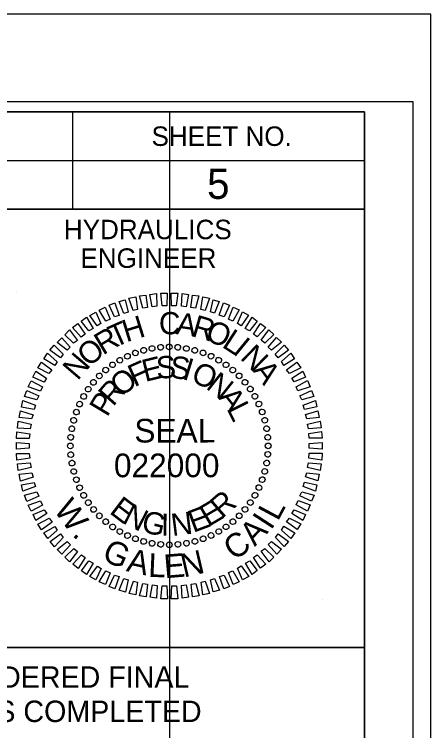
# Model space of a CAD drawing. Extents: x 10070 to 15319, y 8517 to 10343.
# Drawn here: x 14785 to 14891.9, y 9432.8 to 9616.7 of the extents above; entities that cross this region are included whole.
import ezdxf

# ---------------------------------------------------------------- set-up
doc = ezdxf.new("R2010")
doc.units = 0
for name, color, linetype in [('Default', 7, 'Continuous'), ('Scratch_Level_3', 7, 'Continuous'), ('Scratch_Level_4', 7, 'Continuous'), ('Sheet Cutting Line CELL', 7, 'Continuous'), ('Sheet Data Field CELL', 7, 'Continuous'), ('Sheet Plot Border Inside CELL', 7, 'Continuous'), ('Sheet Plot Border Outside CELL', 7, 'Continuous'), ('Sheet Profile CELL', 7, 'Continuous'), ('Sheet Profile Grid Major CELL', 7, 'Continuous'), ('Sheet Sticker Exception Certification CELL', 7, 'Continuous')]:
    doc.layers.add(name, color=color, linetype=linetype)

msp = doc.modelspace()

# ---------------------------------------------------------------- linework, layer by layer
at = {"layer": 'Default'}
for p, q in [((14785.51, 9545.45), (14785.51, 9545.45)), ((14818.22, 9530.48), (14818.22, 9530.48)), ((14820.4, 9530.94), (14820.4, 9530.94)), ((14829.21, 9530.94), (14829.21, 9530.94)), ((14814.07, 9528.96), (14814.07, 9528.96)), ((14816.09, 9529.82), (14816.09, 9529.82)), ((14841.16, 9525.43), (14841.16, 9525.43)), ((14806.83, 9523.9), (14806.83, 9523.9)), ((14805.31, 9522.28), (14805.31, 9522.28)), ((14804, 9520.5), (14804, 9520.5)), ((14845.61, 9520.52), (14845.61, 9520.52)), ((14802.78, 9518.63), (14802.78, 9518.63)), ((14846.83, 9518.65), (14846.83, 9518.65)), ((14801.77, 9516.66), (14801.77, 9516.66)), ((14847.84, 9516.67), (14847.84, 9516.67)), ((14800.91, 9514.63), (14800.91, 9514.63)), ((14848.7, 9514.65), (14848.7, 9514.65)), ((14800.26, 9512.5), (14800.26, 9512.5)), ((14849.36, 9512.52), (14849.36, 9512.52)), ((14799.8, 9510.33), (14799.8, 9510.33)), ((14849.82, 9510.35), (14849.82, 9510.35)), ((14799.5, 9508.15), (14799.5, 9508.15)), ((14850.12, 9508.17), (14850.12, 9508.17)), ((14799.4, 9505.92), (14799.4, 9505.92)), ((14824.81, 9505.93), (14824.81, 9505.93)), ((14850.23, 9505.94), (14850.23, 9505.94)), ((14799.5, 9503.69), (14799.5, 9503.69)), ((14850.13, 9503.72), (14850.13, 9503.72)), ((14799.81, 9501.52), (14799.81, 9501.52)), ((14849.82, 9501.54), (14849.82, 9501.54)), ((14800.26, 9499.34), (14800.26, 9499.34)), ((14849.37, 9499.36), (14849.37, 9499.36)), ((14800.92, 9497.21), (14800.92, 9497.21)), ((14848.71, 9497.23), (14848.71, 9497.23)), ((14801.78, 9495.19), (14801.78, 9495.19)), ((14847.85, 9495.21), (14847.85, 9495.21)), ((14802.8, 9493.22), (14802.8, 9493.22)), ((14846.84, 9493.23), (14846.84, 9493.23)), ((14804.01, 9491.34), (14804.01, 9491.34)), ((14845.62, 9491.36), (14845.62, 9491.36)), ((14805.33, 9489.57), (14805.33, 9489.57)), ((14844.31, 9489.59), (14844.31, 9489.59)), ((14806.85, 9487.95), (14806.85, 9487.95)), ((14808.47, 9486.43), (14808.47, 9486.43)), ((14841.17, 9486.45), (14841.17, 9486.45)), ((14842.79, 9487.97), (14842.79, 9487.97)), ((14810.24, 9485.12), (14810.24, 9485.12)), ((14839.4, 9485.13), (14839.4, 9485.13)), ((14812.11, 9483.91), (14812.11, 9483.91)), ((14814.09, 9482.89), (14814.09, 9482.89)), ((14835.55, 9482.9), (14835.55, 9482.9)), ((14837.53, 9483.92), (14837.53, 9483.92)), ((14816.11, 9482.03), (14816.11, 9482.03)), ((14818.24, 9481.38), (14818.24, 9481.38)), ((14820.42, 9480.92), (14820.42, 9480.92)), ((14829.23, 9480.93), (14829.23, 9480.93)), ((14831.4, 9481.38), (14831.4, 9481.38)), ((14833.53, 9482.04), (14833.53, 9482.04)), ((14822.59, 9480.62), (14822.59, 9480.62)), ((14824.82, 9480.52), (14824.82, 9480.52)), ((14827.05, 9480.62), (14827.05, 9480.62)), ((14864.11, 9466.41), (14864.11, 9466.41))]:
    msp.add_line(p, q, dxfattribs=at)
for points in [[(14820.44, 9541.62), (14819.83, 9544.81), (14821.51, 9545.06), (14821.66, 9541.77)], [(14822.97, 9541.88), (14822.62, 9545.17), (14824.29, 9545.17), (14824.19, 9541.88)], [(14825.4, 9541.88), (14825.3, 9545.17), (14826.97, 9545.17), (14826.62, 9541.88)], [(14827.94, 9541.78), (14828.09, 9545.07), (14829.76, 9544.81), (14829.15, 9541.62)], [(14813.15, 9539.95), (14811.94, 9542.98), (14813.51, 9543.44), (14814.22, 9540.3)], [(14815.58, 9540.66), (14814.47, 9543.85), (14816.19, 9544.2), (14816.65, 9540.91)], [(14818.01, 9541.27), (14817.15, 9544.45), (14818.82, 9544.66), (14819.23, 9541.42)], [(14830.37, 9541.42), (14830.77, 9544.66), (14832.44, 9544.46), (14831.58, 9541.27)], [(14832.95, 9540.92), (14833.4, 9544.21), (14835.12, 9543.85), (14834.01, 9540.66)], [(14835.38, 9540.31), (14836.09, 9543.45), (14837.66, 9542.99), (14836.44, 9539.96)], [(14808.5, 9537.97), (14806.83, 9540.81), (14808.39, 9541.51), (14809.61, 9538.48)], [(14810.72, 9539.09), (14809.36, 9542.02), (14810.82, 9542.63), (14811.94, 9539.44)], [(14837.66, 9539.45), (14838.77, 9542.64), (14840.24, 9542.03), (14838.87, 9539.1)], [(14839.99, 9538.49), (14841.2, 9541.53), (14842.77, 9540.82), (14841.1, 9537.98)], [(14806.32, 9536.76), (14804.4, 9539.44), (14805.97, 9540.3), (14807.28, 9537.36)], [(14842.32, 9537.38), (14843.63, 9540.31), (14845.2, 9539.45), (14843.28, 9536.77)], [(14804.14, 9535.44), (14802.22, 9537.97), (14803.54, 9538.98), (14805.26, 9536.05)], [(14844.34, 9536.06), (14846.06, 9539), (14847.38, 9537.99), (14845.45, 9535.46)], [(14802.22, 9533.87), (14799.99, 9536.3), (14801.36, 9537.36), (14803.18, 9534.58)], [(14846.42, 9534.59), (14848.24, 9537.38), (14849.61, 9536.32), (14847.38, 9533.89)], [(14800.25, 9532.3), (14797.97, 9534.47), (14799.18, 9535.69), (14801.21, 9533.01)], [(14848.39, 9533.03), (14850.42, 9535.71), (14851.63, 9534.5), (14849.35, 9532.32)], [(14798.58, 9530.47), (14796, 9532.5), (14797.21, 9533.71), (14799.39, 9531.28)], [(14850.22, 9531.31), (14852.39, 9533.74), (14853.61, 9532.52), (14851.03, 9530.5)], [(14796.86, 9528.5), (14794.17, 9530.47), (14795.29, 9531.79), (14797.57, 9529.46)], [(14852.04, 9529.48), (14854.32, 9531.81), (14855.43, 9530.5), (14852.75, 9528.52)], [(14795.39, 9526.57), (14792.61, 9528.24), (14793.57, 9529.71), (14796, 9527.54)], [(14853.61, 9527.56), (14856.04, 9529.74), (14857, 9528.27), (14854.22, 9526.6)], [(14793.92, 9524.5), (14791.04, 9525.97), (14792, 9527.43), (14794.68, 9525.46)], [(14854.93, 9525.49), (14857.61, 9527.46), (14858.57, 9525.99), (14855.69, 9524.52)], [(14792.71, 9522.32), (14789.82, 9523.54), (14790.53, 9525.1), (14793.32, 9523.28)], [(14856.29, 9523.31), (14859.08, 9525.13), (14859.79, 9523.56), (14856.9, 9522.35)], [(14791.75, 9519.99), (14788.61, 9521.1), (14789.32, 9522.67), (14792.25, 9521.11)], [(14857.36, 9521.13), (14860.29, 9522.7), (14861, 9521.13), (14857.86, 9520.02)], [(14790.79, 9517.71), (14787.65, 9518.57), (14788.25, 9520.14), (14791.29, 9518.78)], [(14858.32, 9518.8), (14861.36, 9520.17), (14861.97, 9518.6), (14858.83, 9517.74)], [(14790.08, 9515.28), (14786.89, 9515.89), (14787.24, 9517.56), (14790.43, 9516.35)], [(14859.18, 9516.38), (14862.37, 9517.59), (14862.73, 9515.92), (14859.54, 9515.31)], [(14789.47, 9512.85), (14786.28, 9513.21), (14786.64, 9514.93), (14789.83, 9513.92)], [(14859.79, 9513.95), (14862.98, 9514.96), (14863.33, 9513.24), (14860.15, 9512.88)], [(14789.07, 9510.27), (14785.83, 9510.52), (14786.03, 9512.24), (14789.32, 9511.49)], [(14860.3, 9511.52), (14863.59, 9512.28), (14863.79, 9510.56), (14860.55, 9510.3)], [(14788.87, 9507.84), (14785.58, 9507.84), (14785.68, 9509.56), (14788.97, 9509.06)], [(14860.65, 9509.09), (14863.94, 9509.59), (14864.05, 9507.87), (14860.75, 9507.87)], [(14788.87, 9505.31), (14785.58, 9505.06), (14785.58, 9506.78), (14788.87, 9506.52)], [(14860.76, 9506.55), (14864.05, 9506.81), (14864.05, 9505.09), (14860.76, 9505.34)], [(14788.97, 9502.78), (14785.68, 9502.27), (14785.58, 9503.99), (14788.87, 9503.99)], [(14860.76, 9504.02), (14864.05, 9504.02), (14863.95, 9502.3), (14860.66, 9502.81)], [(14789.33, 9500.35), (14786.04, 9499.59), (14785.83, 9501.31), (14789.07, 9501.56)], [(14860.56, 9501.59), (14863.8, 9501.34), (14863.59, 9499.62), (14860.3, 9500.38)], [(14789.83, 9497.92), (14786.64, 9496.91), (14786.29, 9498.63), (14789.48, 9498.98)], [(14860.15, 9499.01), (14863.34, 9498.66), (14862.99, 9496.94), (14859.8, 9497.95)], [(14790.44, 9495.49), (14787.25, 9494.27), (14786.9, 9495.94), (14790.09, 9496.55)], [(14859.54, 9496.58), (14862.73, 9495.97), (14862.38, 9494.3), (14859.19, 9495.52)], [(14791.3, 9493.06), (14788.27, 9491.69), (14787.66, 9493.26), (14790.8, 9494.12)], [(14858.84, 9494.15), (14861.98, 9493.29), (14861.37, 9491.72), (14858.33, 9493.09)], [(14792.27, 9490.73), (14789.33, 9489.16), (14788.62, 9490.73), (14791.76, 9491.84)], [(14857.88, 9491.87), (14861.02, 9490.76), (14860.31, 9489.19), (14857.37, 9490.76)], [(14793.33, 9488.55), (14790.55, 9486.73), (14789.84, 9488.3), (14792.72, 9489.52)], [(14856.92, 9489.54), (14859.8, 9488.33), (14859.09, 9486.76), (14856.31, 9488.58)], [(14794.7, 9486.38), (14792.02, 9484.4), (14791.05, 9485.87), (14793.94, 9487.34)], [(14855.7, 9487.37), (14858.59, 9485.9), (14857.63, 9484.43), (14854.94, 9486.4)], [(14796.02, 9484.3), (14793.59, 9482.13), (14792.62, 9483.59), (14795.41, 9485.26)], [(14854.23, 9485.29), (14857.02, 9483.62), (14856.06, 9482.15), (14853.63, 9484.33)], [(14797.59, 9482.38), (14795.31, 9480.05), (14794.19, 9481.37), (14796.88, 9483.34)], [(14852.77, 9483.36), (14855.45, 9481.39), (14854.34, 9480.07), (14852.06, 9482.4)], [(14799.41, 9480.56), (14797.23, 9478.13), (14796.02, 9479.34), (14798.6, 9481.37)], [(14851.05, 9481.39), (14853.63, 9479.37), (14852.41, 9478.15), (14850.24, 9480.58)], [(14801.23, 9478.84), (14799.21, 9476.15), (14797.99, 9477.37), (14800.27, 9479.55)], [(14849.38, 9479.57), (14851.66, 9477.39), (14850.44, 9476.18), (14848.41, 9478.86)], [(14803.21, 9477.27), (14801.39, 9474.48), (14800.02, 9475.55), (14802.24, 9477.98)], [(14847.4, 9478), (14849.63, 9475.57), (14848.26, 9474.5), (14846.44, 9477.29)], [(14805.28, 9475.8), (14803.56, 9472.87), (14802.25, 9473.88), (14804.17, 9476.41)], [(14845.48, 9476.43), (14847.4, 9473.9), (14846.09, 9472.88), (14844.37, 9475.82)], [(14807.31, 9474.49), (14805.99, 9471.55), (14804.42, 9472.41), (14806.35, 9475.09)], [(14809.64, 9473.37), (14808.42, 9470.34), (14806.85, 9471.04), (14808.52, 9473.88)], [(14841.13, 9473.89), (14842.8, 9471.06), (14841.23, 9470.35), (14840.01, 9473.39)], [(14843.3, 9475.11), (14845.23, 9472.43), (14843.66, 9471.57), (14842.34, 9474.5)], [(14811.97, 9472.41), (14810.85, 9469.22), (14809.39, 9469.83), (14810.75, 9472.77)], [(14814.25, 9471.55), (14813.54, 9468.41), (14811.97, 9468.87), (14813.18, 9471.91)], [(14836.47, 9471.92), (14837.69, 9468.88), (14836.12, 9468.42), (14835.41, 9471.56)], [(14838.9, 9472.78), (14840.27, 9469.84), (14838.8, 9469.23), (14837.68, 9472.42)], [(14816.68, 9470.95), (14816.22, 9467.66), (14814.5, 9468.01), (14815.61, 9471.2)], [(14819.26, 9470.44), (14818.85, 9467.2), (14817.18, 9467.4), (14818.04, 9470.59)], [(14821.69, 9470.09), (14821.54, 9466.8), (14819.87, 9467.05), (14820.47, 9470.24)], [(14824.22, 9469.99), (14824.32, 9466.7), (14822.65, 9466.7), (14823, 9469.99)], [(14826.65, 9469.99), (14827.01, 9466.7), (14825.33, 9466.7), (14825.43, 9469.99)], [(14829.18, 9470.24), (14829.79, 9467.05), (14828.12, 9466.8), (14827.97, 9470.09)], [(14831.61, 9470.6), (14832.47, 9467.41), (14830.8, 9467.21), (14830.4, 9470.45)], [(14834.04, 9471.21), (14835.16, 9468.02), (14833.43, 9467.66), (14832.98, 9470.95)]]:
    msp.add_lwpolyline(points, close=True, dxfattribs=at)
for centre, major_axis in [((14816.12, 9529.79), (-0.25, 0.685)), ((14818.23, 9530.46), (-0.189, 0.704)), ((14820.39, 9530.94), (-0.127, 0.718)), ((14822.59, 9531.23), (-0.064, 0.726)), ((14824.8, 9531.33), (0, 0.729)), ((14827.01, 9531.23), (0.063, 0.726)), ((14829.21, 9530.94), (0.126, 0.718)), ((14831.37, 9530.46), (0.188, 0.704)), ((14833.49, 9529.8), (0.249, 0.685)), ((14812.11, 9527.92), (-0.365, 0.631)), ((14814.07, 9528.94), (-0.308, 0.661)), ((14835.53, 9528.95), (0.308, 0.661)), ((14837.5, 9527.93), (0.364, 0.631)), ((14810.24, 9526.73), (-0.418, 0.597)), ((14839.37, 9526.74), (0.418, 0.597)), ((14808.48, 9525.38), (-0.469, 0.558)), ((14841.13, 9525.39), (0.468, 0.559)), ((14805.35, 9522.25), (-0.559, 0.468)), ((14806.85, 9523.88), (-0.516, 0.515)), ((14842.76, 9523.9), (0.515, 0.516)), ((14844.26, 9522.26), (0.558, 0.469)), ((14804, 9520.49), (-0.597, 0.418)), ((14845.61, 9520.51), (0.597, 0.418)), ((14802.82, 9518.62), (-0.631, 0.364)), ((14846.8, 9518.64), (0.631, 0.365)), ((14801.79, 9516.65), (-0.661, 0.308)), ((14847.82, 9516.67), (0.661, 0.308)), ((14800.95, 9514.61), (-0.685, 0.249)), ((14848.67, 9514.63), (0.685, 0.25)), ((14800.28, 9512.49), (-0.704, 0.188)), ((14849.34, 9512.51), (0.704, 0.189)), ((14799.8, 9510.33), (-0.718, 0.126)), ((14849.82, 9510.35), (0.718, 0.127)), ((14799.51, 9508.13), (-0.726, 0.063)), ((14850.11, 9508.16), (0.726, 0.064)), ((14799.42, 9505.92), (-0.729, 0)), ((14850.21, 9505.94), (0.729, 0)), ((14799.52, 9503.71), (-0.726, -0.064)), ((14850.11, 9503.73), (0.726, -0.063)), ((14799.81, 9501.51), (-0.718, -0.127)), ((14849.82, 9501.53), (0.718, -0.126)), ((14800.29, 9499.35), (-0.704, -0.189)), ((14849.34, 9499.37), (0.704, -0.188)), ((14800.95, 9497.24), (-0.685, -0.25)), ((14848.68, 9497.26), (0.685, -0.249)), ((14801.8, 9495.19), (-0.661, -0.308)), ((14847.83, 9495.21), (0.661, -0.308)), ((14802.83, 9493.23), (-0.631, -0.365)), ((14846.81, 9493.24), (0.631, -0.364)), ((14804.02, 9491.36), (-0.597, -0.418)), ((14845.62, 9491.38), (0.597, -0.418)), ((14805.37, 9489.6), (-0.558, -0.469)), ((14844.27, 9489.62), (0.559, -0.468)), ((14806.86, 9487.97), (-0.515, -0.516)), ((14842.78, 9487.98), (0.516, -0.515)), ((14808.5, 9486.47), (-0.468, -0.559)), ((14841.14, 9486.49), (0.469, -0.558)), ((14810.26, 9485.12), (-0.418, -0.597)), ((14812.12, 9483.94), (-0.364, -0.631)), ((14837.52, 9483.95), (0.365, -0.631)), ((14839.39, 9485.14), (0.418, -0.597)), ((14814.09, 9482.91), (-0.308, -0.661)), ((14816.14, 9482.07), (-0.249, -0.685)), ((14833.51, 9482.07), (0.25, -0.685)), ((14835.55, 9482.92), (0.308, -0.661)), ((14818.25, 9481.4), (-0.188, -0.704)), ((14820.41, 9480.92), (-0.126, -0.718)), ((14822.61, 9480.63), (-0.063, -0.726)), ((14824.82, 9480.54), (0, -0.729)), ((14827.04, 9480.64), (0.064, -0.726)), ((14829.23, 9480.93), (0.127, -0.718)), ((14831.39, 9481.41), (0.189, -0.704))]:
    msp.add_ellipse(centre, major_axis=major_axis, ratio=0.999708, dxfattribs=at)
at = {"layer": 'Scratch_Level_3'}
msp.add_lwpolyline([(13374.94, 9591.73), (14824.91, 9591.73), (14824.91, 8566.73), (13374.94, 8566.73)], close=True, dxfattribs=at)
at = {"layer": 'Scratch_Level_4'}
msp.add_lwpolyline([(13374.94, 9591.73), (14874.94, 9591.73), (14874.94, 9091.73), (13374.94, 9091.73)], close=True, dxfattribs=at)
at = {"layer": 'Sheet Cutting Line CELL'}
msp.add_line((14891.94, 9616.73), (13207.94, 9616.73), dxfattribs=at)
at = {"layer": 'Sheet Plot Border Inside CELL'}
msp.add_lwpolyline([(13220.94, 8539.18), (14887.44, 8539.18), (14887.44, 9594.28), (13220.94, 9594.28)], close=True, dxfattribs=at)
at = {"layer": 'Sheet Plot Border Outside CELL'}
msp.add_lwpolyline([(13207.94, 8516.73), (14891.94, 8516.73), (14891.94, 9616.73), (13207.94, 9616.73)], close=True, dxfattribs=at)
at = {"layer": 'Sheet Profile CELL'}
for p, q in [((14799.94, 9591.68), (14799.94, 9566.68)), ((14674.89, 9579.18), (14874.94, 9579.18))]:
    msp.add_line(p, q, dxfattribs=at)
for points in [[(14874.94, 9591.73), (13374.94, 9591.73), (13374.94, 8541.73), (14874.94, 8541.73)], [(14674.89, 9591.73), (14874.94, 9591.73), (14874.94, 9566.68), (14674.89, 9566.68)], [(14774.94, 9566.68), (14874.94, 9566.68), (14874.94, 9454.18), (14774.94, 9454.18)]]:
    msp.add_lwpolyline(points, close=True, dxfattribs=at)
at = {"layer": 'Sheet Profile Grid Major CELL'}
msp.add_lwpolyline([(14824.94, 9430.68), (14824.94, 9091.73), (14874.94, 9091.73), (14874.94, 9441.73)], dxfattribs=at)
at = {"layer": 'Sheet Sticker Exception Certification CELL'}
for p, q in [((14674.89, 9454.18), (14874.93, 9454.18)), ((14674.89, 9454.18), (14874.93, 9454.18)), ((14874.93, 9454.16), (14874.93, 9430.66)), ((14874.93, 9454.16), (14874.93, 9430.66))]:
    msp.add_line(p, q, dxfattribs=at)

# ---------------------------------------------------------------- texts
at = {"layer": 'Default'}
for s, height, rotation, p in [('C', 5.71, 359.9131, (14822.15, 9534.58)), ('A', 5.71, 351.5841, (14826.33, 9534.66)), ('T', 5.71, 23.8503, (14810.76, 9531.04)), ('H', 5.71, 17.1792, (14813.77, 9532.5)), ('R', 5.71, 343.6971, (14830.26, 9534.18)), ('O', 5.71, 336.6207, (14833.7, 9533.3)), ('R', 5.71, 30.9268, (14807.77, 9529.11)), ('L', 5.71, 327.1126, (14838.1, 9531.45)), ('O', 5.71, 40.4348, (14804.18, 9525.98)), ('I', 5.71, 320.7546, (14840.84, 9529.82)), ('N', 5.71, 315.8704, (14842.82, 9528.37)), ('N', 5.71, 49.4455, (14801.29, 9522.5)), ('E', 5.71, 13.9744, (14818.62, 9522.31)), ('S', 5.71, 3.7775, (14821.62, 9523.14)), ('S', 5.71, 353.3889, (14824.77, 9523.44)), ('F', 5.71, 24.0891, (14815.84, 9520.97)), ('I', 5.71, 343.0002, (14827.93, 9523.16)), ('O', 5.71, 335.7351, (14830.08, 9522.63)), ('A', 5.71, 306.8597, (14846.11, 9525.28)), ('O', 5.71, 38.2317, (14812.44, 9518.32)), ('N', 5.71, 321.5926, (14834, 9520.83)), ('R', 5.71, 48.7574, (14810.38, 9515.85)), ('P', 5.71, 58.9542, (14808.86, 9513.14)), ('A', 5.71, 308.1898, (14837.21, 9518.3)), ('L', 5.71, 296.4585, (14839.46, 9515.52)), ('SEAL', 6.073, 0.0237, (14815.85, 9506.79)), ('022000', 6.075, 0.0237, (14810.6, 9497.88)), ('R', 5.71, 40.8386, (14838.36, 9487.12)), ('W', 6.07, 305.5864, (14794.98, 9489.55)), ('E', 5.71, 322.7747, (14809.2, 9488.79)), ('E', 5.71, 30.6417, (14834.81, 9485.01)), ('N', 5.71, 332.9716, (14812.49, 9486.29)), ('E', 5.71, 20.4448, (14830.95, 9483.57)), ('L', 6.07, 61.8108, (14852.69, 9486.41)), ('G', 5.71, 346.3743, (14817.37, 9483.97)), ('I', 5.71, 359.7771, (14822.67, 9482.85)), ('N', 5.71, 7.0421, (14825.6, 9482.76)), ('I', 6.07, 56.9421, (14850.94, 9484.11)), ('A', 6.07, 46.9863, (14846.77, 9479.93)), ('.', 6.07, 319.2718, (14799.7, 9482.95)), ('C', 6.07, 36.2814, (14841.56, 9476.3)), ('G', 6.07, 335.7036, (14807.23, 9476.79)), ('A', 6.07, 347.5632, (14813.59, 9473.8)), ('N', 6.07, 13.0927, (14828.54, 9472.1)), ('L', 6.07, 357.5191, (14819.32, 9472.34)), ('E', 6.07, 4.8846, (14823.67, 9471.92))]:
    msp.add_text(s, height=height, rotation=rotation, dxfattribs=at).set_placement(p)
at = {"layer": 'Sheet Data Field CELL'}
msp.add_text('5', height=7.75, dxfattribs=at).set_placement((14834.52, 9569.34))
at = {"layer": 'Sheet Profile CELL'}
for s, p in [('SHEET NO.', (14820.25, 9582.94)), ('HYDRAULICS', (14797.75, 9558.99)), ('ENGINEER', (14802, 9551.64))]:
    msp.add_text(s, height=5, dxfattribs=at).set_placement(p)
at = {"layer": 'Sheet Sticker Exception Certification CELL'}
for s, p in [('DOCUMENT NOT CONSIDERED FINAL', (14695.96, 9443.83)), ('DOCUMENT NOT CONSIDERED FINAL', (14695.96, 9443.83)), ('UNLESS ALL SIGNATURES COMPLETED', (14690.89, 9435.03)), ('UNLESS ALL SIGNATURES COMPLETED', (14690.89, 9435.03))]:
    msp.add_text(s, height=5.5, dxfattribs=at).set_placement(p)

doc.saveas('drawing.dxf')
